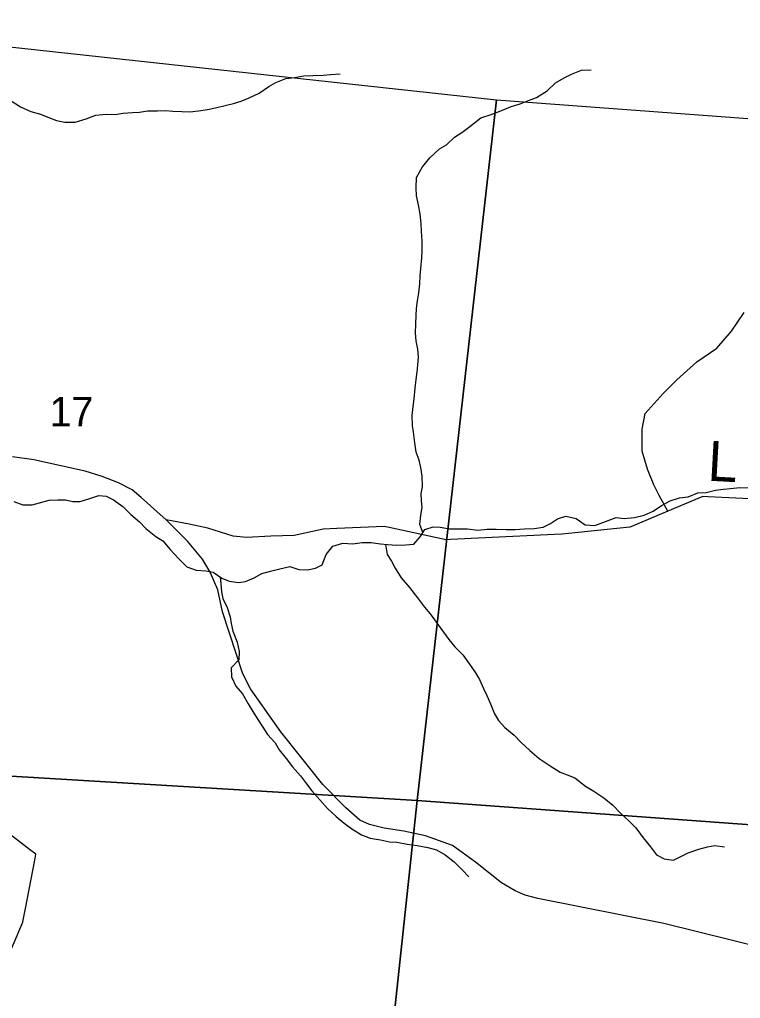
# Model space of a CAD drawing. Extents: x 1715311 to 2083412, y 146837 to 553079.
# Drawn here: x 1933252 to 1938656, y 419778 to 427121 of the extents above; entities that cross this region are included whole.
import ezdxf

# ---------------------------------------------------------------- set-up
doc = ezdxf.new("R2010")
doc.units = 0
for name, color, linetype in [('GM_X_County_Road', 7, 'Continuous'), ('GM_X_County_Road_Text', 7, 'Continuous'), ('GM_X_Minor_River', 7, 'Continuous'), ('GM_X_Section', 7, 'Continuous'), ('GM_X_Section_Text', 7, 'Continuous'), ('GM_X_State_Route', 7, 'Continuous'), ('GM_X_Township_ROW', 7, 'Continuous')]:
    doc.layers.add(name, color=color, linetype=linetype)

msp = doc.modelspace()

# ---------------------------------------------------------------- linework, layer by layer
at = {"layer": 'GM_X_County_Road'}
for points in [[(1938830.1, 423519.7), (1938413.4, 423540.9), (1938373.5, 423542.9), (1938314.2, 423517.9), (1938112.5, 423432.9), (1937833.8, 423315.3), (1937827.5, 423312.6), (1937730.5, 423302.7), (1937367.4, 423265.5), (1937319.4, 423260.6), (1937263.3, 423257.8), (1936482.2, 423220.1), (1936451.2, 423218.5), (1936379.4, 423233.9), (1936022.6, 423310.7), (1935985.1, 423318.7), (1935629.8, 423303.4), (1935527.9, 423298), (1935311.3, 423250.1), (1935135.8, 423244.1), (1934952, 423236.2), (1934853.2, 423246.1), (1934663.6, 423306.1), (1934523.2, 423335.2), (1934351.9, 423368.8)], [(1933131.1, 420008.9), (1933275.1, 420348.9), (1933276.7, 420352.5), (1933295.9, 420452.2), (1933366.1, 420814.8), (1933374.7, 420859.3), (1933326.9, 420895.7), (1933033.5, 421119.8)]]:
    msp.add_lwpolyline(points, dxfattribs=at)
at = {"layer": 'GM_X_Minor_River'}
for points in [[(1933187.8, 426511.4), (1933259.6, 426467.2), (1933337.4, 426431), (1933409.3, 426410.8), (1933477.2, 426384.7), (1933529.1, 426364.5), (1933591, 426350.4), (1933668.9, 426350.2), (1933750.8, 426376.1), (1933822.8, 426403.9), (1933900.7, 426409.8), (1933968.6, 426407.6), (1934028.5, 426419.5), (1934098.4, 426423.3), (1934150.4, 426427.2), (1934210.3, 426435.1), (1934286.2, 426434.9), (1934348.1, 426438.8), (1934400.1, 426434.7), (1934468, 426430.5), (1934527.9, 426428.4), (1934593.8, 426436.3), (1934661.8, 426446.1), (1934719.7, 426458), (1934803.6, 426477.8), (1934855.6, 426491.7), (1934913.6, 426509.6), (1934973.5, 426533.5), (1935047.5, 426567.4), (1935121.5, 426619.3), (1935173.5, 426649.2), (1935247.5, 426679), (1935313.4, 426684.9), (1935383.3, 426698.7), (1935451.2, 426700.6), (1935531.2, 426704.4), (1935583.1, 426708.3), (1935655, 426714.1)], [(1936274.6, 423272), (1936253.2, 423331.9), (1936259.4, 423404), (1936269.5, 423460), (1936265.6, 423512), (1936263.7, 423566.1), (1936271.8, 423616.1), (1936270, 423696.2), (1936260.1, 423760.3), (1936248.2, 423814.4), (1936224.4, 423876.5), (1936214.5, 423946.6), (1936204.7, 424024.6), (1936196.8, 424076.7), (1936195, 424150.8), (1936203.1, 424218.8), (1936211.2, 424274.9), (1936217.4, 424354.9), (1936225.5, 424421), (1936231.6, 424477), (1936237.7, 424527), (1936243.9, 424591.1), (1936238, 424649.1), (1936226.1, 424711.2), (1936220.3, 424769.3), (1936222.4, 424839.3), (1936226.5, 424901.4), (1936228.6, 424953.4), (1936234.7, 425011.5), (1936244.8, 425071.5), (1936253, 425137.5), (1936255.1, 425197.6), (1936259.2, 425253.6), (1936267.4, 425333.7), (1936271.5, 425385.7), (1936269.6, 425459.8), (1936265.8, 425531.8), (1936263.9, 425589.9), (1936256, 425662), (1936242.2, 425732), (1936228.4, 425798.1), (1936224.5, 425858.2), (1936226.7, 425936.3), (1936272.8, 426016.2), (1936326.8, 426082.2), (1936400.9, 426150.1), (1936452.9, 426180), (1936512.9, 426237.9), (1936568.9, 426273.8), (1936626.9, 426319.7), (1936710.9, 426383.6), (1936786.9, 426409.4), (1936872.9, 426441.3), (1936938.8, 426469.1), (1937004.8, 426489), (1937066.7, 426512.9), (1937126.7, 426534.8), (1937206.7, 426586.6), (1937270.8, 426646.5), (1937334.8, 426682.4), (1937388.7, 426712.3), (1937464.7, 426740.2), (1937538.6, 426744)], [(1933209.6, 423504.8), (1933275.4, 423480.6), (1933347.3, 423480.4), (1933401.3, 423496.3), (1933473.2, 423516.2), (1933539.2, 423518), (1933597.1, 423517.9), (1933651, 423505.8), (1933704.9, 423505.7), (1933778.9, 423527.5), (1933846.8, 423551.4), (1933900.7, 423545.3), (1933956.6, 423517.1), (1934026.4, 423468.9), (1934086.2, 423408.7), (1934150, 423352.5), (1934197.8, 423302.4), (1934273.6, 423242.2), (1934325.5, 423210), (1934381.3, 423145.9), (1934447, 423075.6), (1934506.8, 423015.5), (1934576.7, 422989.3), (1934648.6, 422985.1), (1934702.5, 422975), (1934768.3, 422930.8), (1934824.2, 422906.7), (1934894.1, 422896.5), (1934946, 422906.4), (1935010, 422932.3), (1935068, 422964.2), (1935132, 422982.1), (1935201.9, 422999.9), (1935277.9, 423017.8), (1935345.7, 422995.6), (1935411.6, 422993.5), (1935469.6, 423005.3), (1935521.6, 423031.2), (1935549.7, 423107.2), (1935601.7, 423169.2), (1935675.7, 423193.1), (1935749.6, 423186.9), (1935821.5, 423198.7), (1935887.4, 423196.6), (1935957.3, 423188.4), (1936009.2, 423182.3), (1936081.1, 423178.1), (1936147.1, 423180), (1936209, 423185.9), (1936255, 423239.8), (1936289.1, 423295.8), (1936353.1, 423315.7), (1936405, 423311.6), (1936474.9, 423301.4), (1936558.8, 423301.2), (1936610.7, 423299.1), (1936686.6, 423290.9), (1936758.5, 423296.8), (1936824.4, 423296.6), (1936900.3, 423294.5), (1936968.2, 423296.3), (1937038.1, 423300.2), (1937110, 423304), (1937178, 423313.9), (1937232, 423339.8), (1937286, 423375.7), (1937347.9, 423395.6), (1937425.8, 423377.4), (1937493.6, 423331.2), (1937565.5, 423325), (1937725.4, 423384.7), (1937785.3, 423376.6), (1937863.2, 423386.4), (1937935.2, 423402.3), (1938001.2, 423432.2), (1938065.2, 423474.1), (1938129.1, 423510), (1938199.1, 423531.8), (1938265, 423539.7), (1938337, 423569.6), (1938398.9, 423573.4), (1938468.9, 423589.3), (1938530.8, 423599.1), (1938582.7, 423603), (1938652.7, 423610.9), (1938726.6, 423608.7)], [(1935994.6, 423184), (1936009.1, 423108.2), (1936040.9, 423058.1), (1936066.8, 423004), (1936112.6, 422933.9), (1936176.4, 422859.7), (1936234.1, 422781.5), (1936287.9, 422713.3), (1936329.7, 422663.1), (1936383.5, 422591), (1936429.3, 422524.8), (1936469.2, 422470.6), (1936515, 422414.5), (1936574.8, 422356.3), (1936624.6, 422286.1), (1936670.4, 422220), (1936700.2, 422169.9), (1936730.1, 422101.8), (1936753.9, 422049.6), (1936781.8, 421987.5), (1936813.6, 421913.4), (1936843.4, 421861.3), (1936889.2, 421809.1), (1936961, 421752.9), (1937010.9, 421700.8), (1937078.6, 421636.5), (1937146.4, 421578.3), (1937230.2, 421522.1), (1937306, 421475.9), (1937357.9, 421453.8), (1937413.8, 421431.6), (1937495.5, 421369.4), (1937557.4, 421331.2), (1937631.2, 421283), (1937699, 421226.8), (1937756.8, 421166.6), (1937822.6, 421106.4), (1937872.4, 421056.3), (1937926.2, 420982.1), (1937982, 420913.9), (1938027.8, 420853.7), (1938083.6, 420823.6), (1938155.5, 420815.4), (1938209.5, 420843.3), (1938265.5, 420869.2), (1938343.5, 420897.1), (1938409.4, 420915), (1938465.4, 420924.8), (1938537.2, 420914.7)], [(1934756.8, 422938.5), (1934760.3, 422890.8), (1934766.1, 422826.7), (1934776, 422776.6), (1934807.8, 422710.5), (1934829.7, 422640.4), (1934837.5, 422590.3), (1934851.4, 422532.3), (1934883.2, 422450.1), (1934899, 422380), (1934896.9, 422318), (1934838.8, 422258), (1934840.7, 422190), (1934872.5, 422119.8), (1934924.3, 422061.7), (1934966.1, 421987.5), (1935007.9, 421917.3), (1935043.8, 421863.2), (1935075.6, 421813.1), (1935109.5, 421757), (1935167.2, 421694.8), (1935197.1, 421642.7), (1935250.9, 421578.5), (1935298.7, 421514.3), (1935358.5, 421448.1), (1935402.3, 421388), (1935442.1, 421335.8), (1935501.9, 421267.7), (1935559.7, 421201.5), (1935625.5, 421143.3), (1935685.3, 421093.1), (1935743.2, 421050.9), (1935815, 421004.7), (1935880.8, 420980.6), (1935956.7, 420966.4), (1936024.6, 420952.2), (1936080.5, 420950.1), (1936158.4, 420935.9), (1936232.3, 420923.7), (1936312.1, 420909.5), (1936378, 420893.4), (1936441.8, 420855.2), (1936509.6, 420801), (1936569.5, 420742.8), (1936619.3, 420688.7)]]:
    msp.add_lwpolyline(points, dxfattribs=at)
at = {"layer": 'GM_X_Section'}
for points in [[(1936826.5, 426519.5), (1936232.9, 421261.4), (1930350.1, 421616), (1930732, 424447.5), (1931291.6, 427120.6)], [(1941608.9, 426162.4), (1941173.3, 420902.1), (1936232.9, 421261.4), (1936826.5, 426519.5)], [(1936232.9, 421261.4), (1935665.2, 415965.2), (1929597.5, 416529), (1930350.1, 421616)], [(1936232.9, 421261.4), (1941173.3, 420902.1), (1940243.5, 415602.1), (1935665.2, 415965.2)]]:
    msp.add_lwpolyline(points, close=True, dxfattribs=at)
at = {"layer": 'GM_X_State_Route'}
msp.add_lwpolyline([(1938849.7, 420150.6), (1938083.2, 420338.6), (1937137.9, 420526.3), (1937042.9, 420552.4), (1936966.9, 420585.7), (1936864.7, 420645.1), (1936670, 420799.5), (1936497.7, 420925.6), (1936296.5, 420996.6), (1936133.8, 421032.1), (1935985.9, 421055.8), (1935876.4, 421082.4), (1935802.5, 421115), (1935699, 421206.7), (1935524.4, 421381.3), (1935210.8, 421777.9), (1934983, 422100.4), (1934926.8, 422212.9), (1934774.2, 422676.7), (1934738.6, 422842.8), (1934681.3, 422975.2), (1934624, 423072.1), (1934510.8, 423207.2), (1934351.9, 423368.8), (1934164.7, 423535.7), (1934096.7, 423591.7), (1933994.6, 423645.9), (1933871.7, 423693.8), (1933742.5, 423733.4), (1933359.2, 423818.8), (1933199.2, 423840.6)], dxfattribs=at)
at = {"layer": 'GM_X_Township_ROW'}
msp.add_lwpolyline([(1938112.5, 423432.9), (1938046, 423551.4), (1938006.6, 423630.3), (1937959.3, 423748.6), (1937919.8, 423882.7), (1937919.8, 424048.4), (1937943.5, 424166.7), (1938077.6, 424316.6), (1938180.1, 424419.1), (1938329.9, 424553.2), (1938479.8, 424655.7), (1938590.3, 424781.9), (1938684.9, 424923.9)], dxfattribs=at)

# ---------------------------------------------------------------- texts
at = {"layer": 'GM_X_County_Road_Text'}
msp.add_text('L', height=300, rotation=356.87413, dxfattribs=at).set_placement((1938406.2, 423662))
at = {"layer": 'GM_X_Section_Text'}
msp.add_text('17', height=221, rotation=0.00001, dxfattribs=at).set_placement((1933476.2, 424068.6))

doc.saveas('drawing.dxf')
